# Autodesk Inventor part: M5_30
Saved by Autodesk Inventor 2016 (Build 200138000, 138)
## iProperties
Created: 2015-11
Part Number: M5_30
Material: Generic
Document SubType Name: Modeling
Designer: John
Density: 1 g/cm^3
Appearance: Default
Author: John
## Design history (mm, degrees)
feature "Base1"
body "Solid1"
